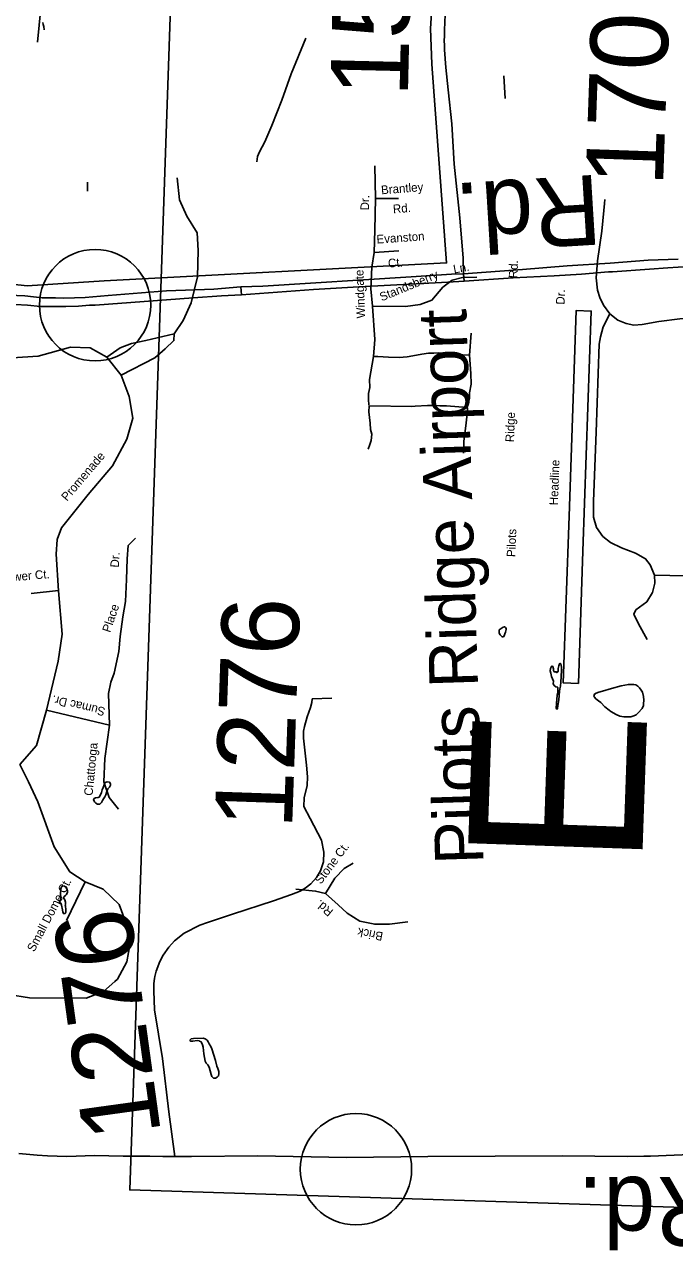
# Model space of a CAD drawing. Extents: x 2308163 to 2335412, y -96774 to 127732.
# Drawn here: x 2326024.5 to 2326125, y 122975.2 to 123164.6 of the extents above; entities that cross this region are included whole.
import ezdxf

# ---------------------------------------------------------------- set-up
doc = ezdxf.new("R2010")
doc.units = 0
for name, color, linetype in [('Default', 7, 'Continuous'), ('Old_Level_10', 7, 'Continuous'), ('Old_Level_11', 7, 'Continuous'), ('Old_Level_20', 7, 'Continuous'), ('Old_Level_28', 7, 'Continuous'), ('Old_Level_32', 7, 'Continuous'), ('Old_Level_35', 7, 'Continuous'), ('Old_Level_50', 7, 'Continuous'), ('Old_Level_55', 7, 'Continuous'), ('Old_Level_59', 7, 'Continuous'), ('Old_Level_6', 7, 'Continuous'), ('Old_Level_60', 7, 'Continuous'), ('Old_Level_63', 7, 'Continuous'), ('Old_Level_8', 7, 'Continuous')]:
    doc.layers.add(name, color=color, linetype=linetype)

msp = doc.modelspace()

# ---------------------------------------------------------------- linework, layer by layer
at = {"layer": 'Default'}
for centre in [(2326035.37, 123121.24), (2326075.73, 122987.72)]:
    msp.add_circle(centre, 8.61, dxfattribs=at)
at = {"layer": 'Old_Level_28'}
for points in [[(2326120.92, 123128.17), (2326115.06, 123127.75), (2326108.37, 123127.31), (2326101.49, 123126.74), (2326092.38, 123126.08)], [(2326115.38, 123126.4), (2326121.14, 123126.8), (2326123.95, 123127.01), (2326128.75, 123127.31), (2326136.2, 123127.75), (2326145.74, 123128.3)], [(2326125.57, 123128.34), (2326120.92, 123128.17)], [(2326057.93, 123124.07), (2326053.72, 123123.71), (2326046.42, 123123.45), (2326037.41, 123122.75), (2326033.82, 123122.44), (2326030.52, 123122.34), (2326029.25, 123122.38), (2326027.17, 123122.36), (2326024.5, 123122.67), (2326023.28, 123122.71), (2326022.27, 123122.83), (2326020.66, 123122.93), (2326016.97, 123123.46), (2326012.09, 123124), (2326006.74, 123124.52), (2325996.58, 123125.64), (2325989.98, 123126.27), (2325987.61, 123126.7), (2325982.31, 123127.25)], [(2325982.47, 123126), (2325983.17, 123125.9), (2325988.22, 123125.37), (2325995.26, 123124.64), (2326000.82, 123124.11), (2326007.95, 123123.16), (2326012.05, 123122.71), (2326017.07, 123121.99), (2326020.62, 123121.51), (2326022, 123121.39), (2326023.01, 123121.32), (2326024.93, 123121.26), (2326026.92, 123121.02), (2326028.9, 123121.03), (2326030.84, 123121.05), (2326032.8, 123121.09), (2326034.52, 123121.23), (2326035.37, 123121.24), (2326050.55, 123122.36), (2326054.92, 123122.7), (2326058.03, 123122.82)], [(2326092.38, 123126.08), (2326090.52, 123126.04), (2326084.25, 123125.63), (2326061.34, 123124.19), (2326057.93, 123124.07)], [(2326092.46, 123124.97), (2326100.03, 123125.47), (2326106.36, 123125.76), (2326110.59, 123126.02), (2326114.79, 123126.38), (2326115.38, 123126.4)], [(2326058.03, 123122.82), (2326069.16, 123123.68), (2326076.19, 123124.05), (2326089.92, 123124.8), (2326092.46, 123124.97)]]:
    msp.add_lwpolyline(points, dxfattribs=at)
at = {"layer": 'Old_Level_32'}
for points in [[(2326095.68, 123211.05), (2326094.15, 123202.48), (2326092.09, 123190.9), (2326091.43, 123186.3), (2326090.87, 123179.83), (2326090.23, 123173.67), (2326089.64, 123167.63), (2326089.53, 123166.17), (2326089.45, 123164.91), (2326089.43, 123163.77), (2326089.4, 123162.88), (2326089.39, 123162.1), (2326089.41, 123161.41), (2326089.43, 123160.68), (2326089.64, 123157.96), (2326089.97, 123154.49), (2326090.57, 123149.28), (2326090.94, 123143.03), (2326091.78, 123134.73), (2326092.31, 123128.52), (2326092.38, 123126.08)], [(2326092.38, 123126.08), (2326092.46, 123124.97)], [(2326057.93, 123124.07), (2326058.03, 123122.82)], [(2326068.96, 123060.43), (2326068.92, 123059.82), (2326068.71, 123059.09), (2326068.19, 123057.64), (2326067.79, 123056.11), (2326067.61, 123055.41), (2326067.6, 123054.33), (2326068.08, 123050.17)], [(2326068.96, 123060.43), (2326071.98, 123060.49)], [(2326068.08, 123050.17), (2326068.21, 123048.34), (2326068.2, 123047.03), (2326067.72, 123045.09), (2326067.67, 123043.78), (2326068.66, 123041.91), (2326070.38, 123038.57), (2326070.73, 123036.7), (2326070.68, 123035.23), (2326070.22, 123033.82), (2326069.6, 123032.78), (2326068.76, 123031.83), (2326067.88, 123031.13), (2326067.12, 123030.68), (2326065.77, 123030.15), (2326062.98, 123029.21)], [(2326062.98, 123029.21), (2326056.65, 123027.12)], [(2326056.65, 123027.12), (2326052.74, 123025.83), (2326051.56, 123025.43), (2326049.14, 123024.17)], [(2326049.14, 123024.17), (2326047.66, 123023.01), (2326046.78, 123022.04), (2326045.91, 123020.82), (2326045.39, 123019.8), (2326044.8, 123018.3), (2326044.61, 123017.5)], [(2326044.61, 123017.5), (2326044.55, 123017.21), (2326044.48, 123016.42), (2326044.44, 123015.29), (2326044.57, 123012.34), (2326045.8, 123004.82), (2326046.76, 122996.61), (2326047.7, 122989.68)], [(2326047.7, 122989.68), (2326045.85, 122989.67), (2326043.83, 122989.74), (2326039.73, 122989.72), (2326035.27, 122989.82), (2326031.01, 122989.71), (2326028.03, 122989.81), (2326026.39, 122989.89), (2326023.57, 122990.17)], [(2326086.86, 122989.69), (2326074.27, 122989.54), (2326060.57, 122989.77), (2326050.3, 122989.71), (2326047.7, 122989.68)], [(2326117.66, 122989.68), (2326107.65, 122989.79), (2326086.86, 122989.69)], [(2326240.14, 122990.41), (2326235.44, 122990.15), (2326232.79, 122990.14), (2326230.33, 122990.02), (2326211.26, 122990.22), (2326203.09, 122989.99), (2326185.55, 122990.09), (2326166.76, 122990.35), (2326158.56, 122990.22), (2326136.66, 122990.07), (2326128.6, 122990.03), (2326121.26, 122989.72), (2326120.23, 122989.72), (2326117.66, 122989.68)]]:
    msp.add_lwpolyline(points, dxfattribs=at)
at = {"layer": 'Old_Level_35'}
for p, q in [((2326098.61, 123156.7), (2326098.82, 123153.2)), ((2326034.22, 123138.85), (2326034.18, 123140.22)), ((2326093.28, 123113.52), (2326093.53, 123116.91))]:
    msp.add_line(p, q, dxfattribs=at)
for points in [[(2326028.14, 123177.39), (2326028, 123176.2), (2326027.21, 123169.29), (2326026.46, 123161.86)], [(2326060.37, 123143.39), (2326060.51, 123144.2), (2326060.78, 123144.93), (2326061.64, 123146.5), (2326062.71, 123148.98), (2326064.26, 123152.92), (2326065.69, 123156.99), (2326067.97, 123162.5)], [(2326078.42, 123113.33), (2326078.62, 123115.93), (2326078.26, 123121.06), (2326078.02, 123123.76), (2326078.2, 123127.1), (2326078.54, 123129.38), (2326078.66, 123132.85), (2326078.77, 123137.71), (2326078.66, 123142.79)], [(2326039.42, 123110.42), (2326044.59, 123113.12), (2326046.21, 123114.51), (2326047.57, 123115.77), (2326047.6, 123116.82), (2326048.99, 123118.87), (2326050.26, 123121.58), (2326051.19, 123125.62), (2326051.33, 123129.68), (2326051.16, 123132.44), (2326049.54, 123134.99), (2326048.45, 123137.52), (2326048.08, 123140.93)], [(2326078.77, 123137.71), (2326082.31, 123137.71)], [(2326114.97, 123119.91), (2326113.99, 123121.26), (2326113.44, 123122.43), (2326113.08, 123123.55), (2326112.86, 123125.48), (2326113.09, 123128.07), (2326113.74, 123132.65), (2326114.07, 123135.89), (2326114.16, 123136.97), (2326114.24, 123137.57)], [(2326078.54, 123129.38), (2326082.36, 123129.64)], [(2326078.26, 123121.06), (2326083.4, 123121.02), (2326085.66, 123121.32), (2326087.47, 123122.02), (2326089.18, 123124), (2326090.59, 123125.12), (2326092.21, 123125.51), (2326094.43, 123125.56)], [(2326121.91, 123079.52), (2326121.23, 123081.09), (2326120.52, 123082.05), (2326118.96, 123082.91), (2326116.79, 123083.73), (2326115.09, 123084.55), (2326113.92, 123085.47), (2326112.91, 123086.88), (2326112.47, 123088.46), (2326112.48, 123090.96), (2326112.89, 123101.62), (2326113.35, 123115.23), (2326113.53, 123116.36), (2326113.98, 123117.9), (2326114.97, 123119.91)], [(2326151.38, 123094.89), (2326152.61, 123096.68), (2326153.46, 123099.05), (2326153.7, 123101.74), (2326153.93, 123106.83), (2326153.73, 123109.9), (2326153.04, 123112.12), (2326151.98, 123113.94), (2326150.16, 123115.89), (2326148.31, 123116.97), (2326146.55, 123117.59), (2326144.77, 123117.91), (2326137.59, 123118.31), (2326133.47, 123118.5), (2326131.03, 123118.84), (2326128.34, 123119.24), (2326127.35, 123119.23), (2326125.82, 123119.12), (2326122.58, 123118.7), (2326119.97, 123118.27), (2326118.7, 123118.15), (2326117.54, 123118.4), (2326116.24, 123118.92), (2326114.97, 123119.91)], [(2326037.19, 123113.21), (2326039.26, 123114.62), (2326040.99, 123115.34), (2326043.24, 123115.79), (2326047.6, 123116.82)], [(2326022.54, 123113.08), (2326026.55, 123113.34), (2326031.56, 123114.77), (2326034.6, 123114.66), (2326037.19, 123113.21), (2326039.42, 123110.42), (2326040.66, 123107.1), (2326041.19, 123103.8), (2326040.28, 123100.55), (2326038.05, 123096.39), (2326034.3, 123091.96), (2326030.2, 123086.82), (2326029.5, 123085.01), (2326029.34, 123082.77), (2326029.7, 123077.08), (2326030.27, 123070.42), (2326029.65, 123066.21), (2326027.87, 123058.67), (2326026.32, 123053.21), (2326023.73, 123050.26)], [(2326077.71, 123105.8), (2326077.64, 123106.7), (2326077.67, 123107.6), (2326077.86, 123108.52), (2326077.84, 123109.77), (2326078.42, 123113.33)], [(2326078.42, 123113.33), (2326079.09, 123113.31), (2326080.75, 123113.22), (2326082.41, 123113.16), (2326083.63, 123113.28), (2326084.53, 123113.41), (2326085.89, 123113.65), (2326086.95, 123113.81), (2326087.78, 123113.81), (2326088.46, 123113.88), (2326089.45, 123113.82), (2326090.22, 123113.76), (2326091.2, 123113.63), (2326093.28, 123113.52)], [(2326092.94, 123105.47), (2326093.28, 123106.87), (2326093.31, 123107.7), (2326093.54, 123109.03), (2326093.47, 123110.67), (2326093.28, 123113.52)], [(2326077.59, 123098.98), (2326077.88, 123099.72), (2326078.06, 123100.35), (2326078.16, 123101.31), (2326077.99, 123102.02), (2326077.93, 123103.01), (2326077.7, 123104.75), (2326077.77, 123105.67)], [(2326077.83, 123105.7), (2326084.39, 123105.57), (2326084.87, 123105.62), (2326086.77, 123105.75), (2326087.73, 123105.75), (2326088.72, 123105.68), (2326089.74, 123105.68), (2326092.94, 123105.44)], [(2326092.37, 123098.39), (2326092.4, 123099.31), (2326092.43, 123100.24), (2326092.5, 123101.01), (2326092.67, 123102.18), (2326092.93, 123104.38), (2326093, 123105.37)], [(2326037.58, 123056.32), (2326037.43, 123061.24), (2326037.81, 123062.98), (2326038.3, 123064.38), (2326039.07, 123067.74), (2326039.26, 123070.03), (2326039.69, 123073.08), (2326040.1, 123075.47), (2326040.22, 123078.85), (2326040.33, 123082.02), (2326040.51, 123084.09), (2326041.64, 123085.25)], [(2326120.75, 123069.6), (2326119.45, 123072.01), (2326118.68, 123073.51), (2326119.03, 123074.15), (2326120.71, 123075.4), (2326121.57, 123076.84), (2326121.95, 123078.29), (2326121.91, 123079.52)], [(2326121.91, 123079.52), (2326124.26, 123079.45), (2326126.59, 123079.39), (2326127.63, 123079.05), (2326128.49, 123078.5), (2326130.79, 123074.16), (2326130.87, 123072.53), (2326131.32, 123072.02), (2326132.17, 123071.86), (2326132.88, 123072.22), (2326133.32, 123072.91), (2326133.17, 123073.55), (2326132.56, 123074.24), (2326131.92, 123074.37), (2326131.11, 123074.26), (2326130.79, 123074.16)], [(2326025.49, 123076.69), (2326029.7, 123077.15)], [(2326027.87, 123058.67), (2326037.58, 123056.32), (2326036.86, 123051.2), (2326036.74, 123047.6), (2326037.53, 123045.17), (2326039, 123043.37)], [(2326018.69, 123015.24), (2326025.21, 123014.22), (2326034.01, 123014.15), (2326036.69, 123015.18), (2326038.42, 123016.72), (2326038.84, 123017.1), (2326040.29, 123019.77), (2326040.79, 123022.64), (2326040.03, 123026.1), (2326039.08, 123028.61), (2326036.6, 123031.02), (2326033.83, 123032.15), (2326031.49, 123033.67), (2326029.06, 123037.52), (2326026.5, 123044.48), (2326025.08, 123047.57), (2326023.73, 123050.26)], [(2326071.03, 123030.33), (2326072.48, 123032.69), (2326073.89, 123034.21), (2326075.28, 123035)], [(2326030.96, 123026.16), (2326033.83, 123032.15)], [(2326066.45, 123031.01), (2326069.48, 123030.7), (2326071.03, 123030.33), (2326072.96, 123028.59), (2326074.38, 123027.29), (2326076.33, 123026.07), (2326078.62, 123025.57), (2326080.92, 123025.6), (2326083.73, 123025.95)]]:
    msp.add_lwpolyline(points, dxfattribs=at)
at = {"layer": 'Old_Level_50'}
msp.add_lwpolyline([(2325983.15, 123129.04), (2326019.6, 123124.81), (2326024.85, 123124.24), (2326036.79, 123125), (2326089.73, 123127.77), (2326087.47, 123158.5), (2326087.27, 123163.98), (2326087.72, 123171.38), (2326088.58, 123179.16), (2326090.55, 123191.01), (2326093.69, 123208.47), (2326094.21, 123210.48)], dxfattribs=at)
at = {"layer": 'Old_Level_55'}
for points in [[(2326110.84, 123083.2), (2326112.12, 123120.33), (2326109.78, 123120.41), (2326108.68, 123088.64)], [(2326108.68, 123088.64), (2326107.79, 123062.86), (2326110.13, 123062.78), (2326110.84, 123083.2)]]:
    msp.add_lwpolyline(points, dxfattribs=at)
at = {"layer": 'Old_Level_59'}
msp.add_lwpolyline([(2326027.3, 123164.9), (2326027.36, 123164.6), (2326027.47, 123164.31), (2326027.51, 123163.79)], dxfattribs=at)
at = {"layer": 'Old_Level_60'}
for points in [[(2326098.98, 123071.12), (2326098.83, 123070.73), (2326098.61, 123070.05), (2326098.44, 123069.98), (2326098.32, 123069.98), (2326098.03, 123070.3), (2326097.85, 123070.53), (2326097.85, 123070.85), (2326097.89, 123071.05), (2326098.16, 123071.29), (2326098.49, 123071.48), (2326098.68, 123071.55), (2326098.83, 123071.45), (2326098.96, 123071.26), (2326098.98, 123071.12)], [(2326107.52, 123064.81), (2326107.43, 123062.97), (2326107.36, 123062.36), (2326107.25, 123061.95), (2326107.2, 123061.57), (2326107.09, 123060.24), (2326106.93, 123059.33), (2326106.91, 123058.89), (2326106.85, 123058.83), (2326106.71, 123058.89), (2326106.76, 123059.69), (2326106.87, 123060.96), (2326106.93, 123061.33), (2326106.96, 123061.75), (2326106.97, 123062.14), (2326106.91, 123062.21), (2326106.64, 123062.25), (2326106.37, 123062.47), (2326106.23, 123062.71), (2326106.26, 123063.14), (2326105.98, 123063.88), (2326105.85, 123064.35), (2326105.78, 123064.73), (2326105.84, 123065.1), (2326105.97, 123065.42), (2326106.08, 123065.47), (2326106.19, 123065.38), (2326106.26, 123065.02), (2326106.26, 123064.76), (2326106.38, 123064.6), (2326106.71, 123064.59), (2326106.82, 123064.43), (2326106.97, 123064.57), (2326107.02, 123064.73), (2326107.02, 123065.1), (2326107.09, 123065.53), (2326107.23, 123065.82), (2326107.31, 123065.88), (2326107.39, 123065.81), (2326107.5, 123065.32), (2326107.52, 123064.81)], [(2326120.23, 123060.21), (2326120.21, 123059.63), (2326120.18, 123059.36), (2326119.97, 123058.92), (2326119.39, 123058.26), (2326119.07, 123057.95), (2326118.72, 123057.76), (2326118.25, 123057.62), (2326117.74, 123057.61), (2326117.18, 123057.63), (2326116.55, 123057.72), (2326115.98, 123057.96), (2326115.14, 123058.44), (2326114.88, 123058.63), (2326114.23, 123059.18), (2326113.62, 123059.85), (2326113.24, 123060.11), (2326112.85, 123060.42), (2326112.6, 123060.67), (2326112.54, 123060.77), (2326112.6, 123061.13), (2326112.89, 123061.27), (2326113.31, 123061.45), (2326113.84, 123061.58), (2326115.24, 123062.01), (2326116.72, 123062.43), (2326117.86, 123062.63), (2326118.69, 123062.64), (2326118.99, 123062.57), (2326119.32, 123062.38), (2326119.58, 123062.11), (2326119.83, 123061.76), (2326120.03, 123061.43), (2326120.2, 123060.77), (2326120.23, 123060.21)], [(2326037.77, 123047.06), (2326037.62, 123046.78), (2326037.37, 123046.51), (2326037.24, 123046.23), (2326037.16, 123045.91), (2326037.05, 123045.56), (2326036.87, 123045.28), (2326036.7, 123044.96), (2326036.5, 123044.69), (2326036.35, 123044.4), (2326036.26, 123044.26), (2326036.09, 123044.13), (2326035.75, 123044.14), (2326035.47, 123044.27), (2326035.26, 123044.51), (2326035.15, 123044.84), (2326035.23, 123045), (2326035.45, 123045.13), (2326035.84, 123045.15), (2326036, 123045.19), (2326036.23, 123045.55), (2326036.37, 123045.91), (2326036.49, 123046.34), (2326036.62, 123046.73), (2326036.86, 123047.35), (2326036.95, 123047.49), (2326037.25, 123047.58), (2326037.61, 123047.51), (2326037.76, 123047.26), (2326037.77, 123047.06)], [(2326031.13, 123030.51), (2326030.97, 123030.19), (2326030.8, 123030), (2326030.59, 123029.85), (2326030.51, 123029.65), (2326030.71, 123029.34), (2326030.82, 123029), (2326030.8, 123028.66), (2326030.77, 123028.47), (2326030.81, 123028.45), (2326030.86, 123027.75), (2326030.85, 123027.45), (2326030.72, 123027.23), (2326030.54, 123027.2), (2326030.41, 123027.42), (2326030.32, 123027.82), (2326030.2, 123028.54), (2326030.09, 123028.83), (2326030, 123028.9), (2326029.85, 123028.79), (2326029.79, 123028.86), (2326029.96, 123029.17), (2326030.08, 123029.79), (2326030, 123030.22), (2326030.05, 123031.04), (2326030.19, 123031.34), (2326030.38, 123031.5), (2326030.63, 123031.48), (2326030.84, 123031.3), (2326031.01, 123031.04), (2326031.1, 123030.74), (2326031.13, 123030.51)], [(2326051.51, 123007.53), (2326051.47, 123007.56), (2326051.14, 123007.6), (2326050.51, 123007.51), (2326050.18, 123007.49), (2326050.08, 123007.56), (2326050.05, 123007.68), (2326050.25, 123007.85), (2326050.6, 123007.9), (2326052.07, 123007.97), (2326052.41, 123007.89), (2326052.7, 123007.64), (2326052.89, 123007.38), (2326053.04, 123007.1), (2326053.29, 123006.68), (2326053.42, 123006.33), (2326054, 123004.54), (2326054.23, 123003.63), (2326054.38, 123003.27), (2326054.49, 123002.82), (2326054.53, 123002.5), (2326054.48, 123002.13), (2326054.26, 123001.92), (2326053.98, 123001.78), (2326053.7, 123001.8), (2326053.45, 123002.07), (2326053.32, 123002.38), (2326053.01, 123003.49), (2326052.79, 123003.84), (2326052.57, 123004.12), (2326052.4, 123004.42), (2326052.18, 123005.56), (2326052.08, 123006.59), (2326052, 123006.95), (2326051.83, 123007.31), (2326051.76, 123007.38), (2326051.51, 123007.53)]]:
    msp.add_lwpolyline(points, dxfattribs=at)
at = {"layer": 'Old_Level_63'}
msp.add_lwpolyline([(2326216.61, 123246.24), (2326207.41, 122979.25), (2326040.74, 122984.51), (2326051.48, 123296.05)], dxfattribs=at)

# ---------------------------------------------------------------- texts
at = {"layer": 'Old_Level_10'}
for s, height, rotation, p in [('Brantley', 1.333, 4.3646, (2326079.66, 123138.37)), ('Dr.', 1.333, 89.4385, (2326077.75, 123135.88)), ('Rd.', 1.333, 4.3646, (2326081.49, 123135.43)), ('Evanston', 1.333, 3.9715, (2326078.95, 123130.75)), ('Ct.', 1.333, 3.9715, (2326080.72, 123127.05)), ('Ln.', 1.333, 10.8306, (2326090.91, 123126.12)), ('Rd.', 1.333, 87.9298, (2326100.69, 123125.38)), ('Windgate', 1.333, 92.2238, (2326077.16, 123119.22)), ('Standsberry', 1.3328, 22.4236, (2326079.71, 123121.81)), ('Dr.', 1.333, 87.0673, (2326107.97, 123121.29)), ('Ridge', 1.333, 88.0247, (2326100.17, 123100.05)), ('Promenade', 1.333, 49.5056, (2326031.02, 123090.87)), ('Headline', 1.333, 88.0247, (2326106.96, 123090.3)), ('Pilots', 1.333, 87.8633, (2326100.37, 123082.29)), ('Dr.', 1.333, 87.4369, (2326039.06, 123080.67)), ('Tower Ct.', 1.333, 4.9538, (2326020.69, 123078.4)), ('Place', 1.333, 71.0915, (2326037.69, 123070.56)), ('Sumac Dr.', 1.333, 166.5432, (2326037.05, 123059.01)), ('Chattooga', 1.333, 84.5243, (2326034.98, 123045.38)), ('Stone Ct.', 1.333, 52.9539, (2326070.29, 123031.66)), ('Small Dome Ct.', 1.3328, 62.207, (2326025.95, 123021.2)), ('Rd.', 1.333, 140.7679, (2326072.33, 123027.7)), ('Brick', 1.333, 169.0975, (2326080, 123024.3))]:
    msp.add_text(s, height=height, rotation=rotation, dxfattribs=at).set_placement(p)
at = {"layer": 'Old_Level_11'}
msp.add_text('Rd.', height=10.796, rotation=179.9256, dxfattribs=at).set_placement((2326132.44, 122986.51))
at = {"layer": 'Old_Level_20'}
for s, height, rotation, p in [('Pilots Ridge Airport', 7.4972, 91.8048, (2326095.48, 123034.94)), ('E', 26.99, 88.0247, (2326119.96, 123034.21))]:
    msp.add_text(s, height=height, rotation=rotation, dxfattribs=at).set_placement(p)
at = {"layer": 'Old_Level_6'}
msp.add_text('Rd.', height=10.796, rotation=183.5118, dxfattribs=at).set_placement((2326113.25, 123141.42))
at = {"layer": 'Old_Level_8'}
for s, rotation, p in [('1524', 88.6619, (2326083.75, 123153.35)), ('1701', 88.0247, (2326123.22, 123139.5)), ('1276', 88.0247, (2326065.84, 123040.21)), ('1276', 97.8702, (2326045.59, 122993.19))]:
    msp.add_text(s, height=11.996, rotation=rotation, dxfattribs=at).set_placement(p)

doc.saveas('drawing.dxf')
